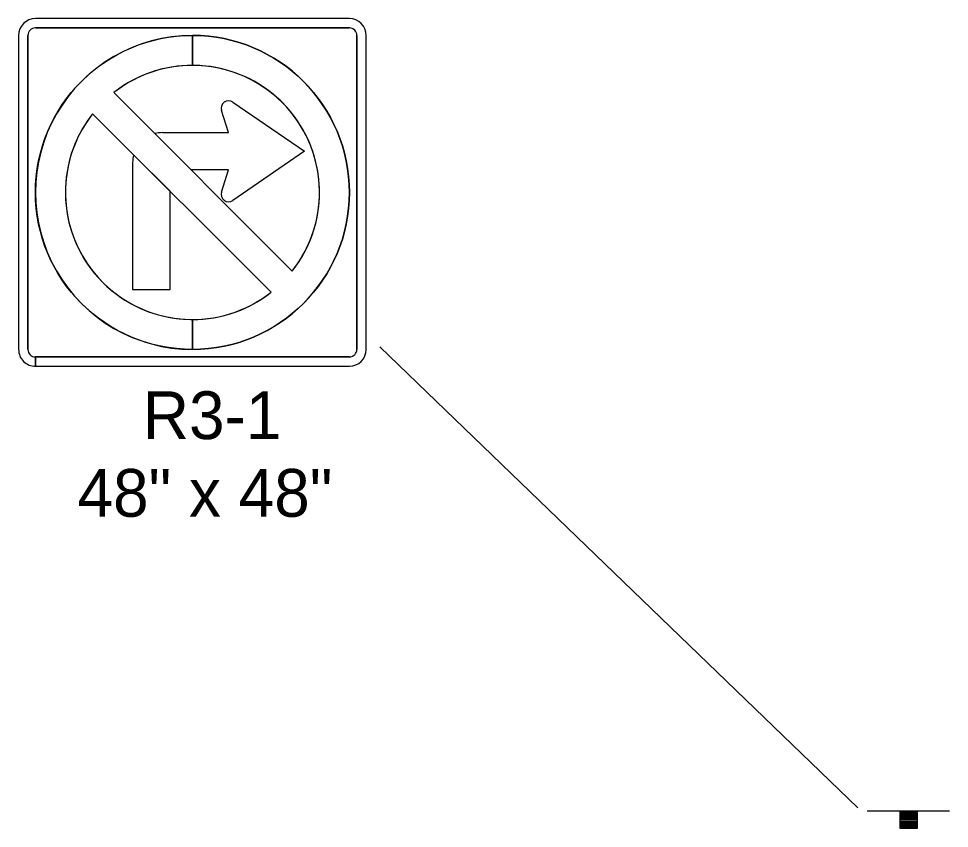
# Model space of a CAD drawing. Extents: x 10124 to 16850, y 7924 to 12166.
# Drawn here: x 12115.7 to 12427.5, y 11894.8 to 12166 of the extents above; entities that cross this region are included whole.
import ezdxf

# ---------------------------------------------------------------- set-up
doc = ezdxf.new("R2010")
doc.units = 0
for name, color, linetype in [('dsnStdLabel', 7, 'Continuous'), ('GSBWFILL', 7, 'Continuous'), ('GSCOLORFILL', 7, 'Continuous'), ('GSOUTLINE', 7, 'Continuous'), ('Level 2', 7, 'Continuous')]:
    doc.layers.add(name, color=color, linetype=linetype)

msp = doc.modelspace()

# ---------------------------------------------------------------- linework, layer by layer
at = {"layer": 'dsnStdLabel'}
for p, q in [((12226.51, 12165.98), (12121.35, 12165.98)), ((12226.51, 12165.98), (12121.35, 12165.98)), ((12121.35, 12165.98), (12121.35, 12165.97)), ((12226.51, 12165.98), (12121.35, 12165.98)), ((12121.35, 12165.98), (12121.35, 12165.97)), ((12226.51, 12165.98), (12226.51, 12165.98)), ((12226.51, 12165.98), (12226.51, 12165.98)), ((12226.51, 12162.85), (12121.35, 12162.85)), ((12121.35, 12162.84), (12121.36, 12162.85)), ((12121.35, 12162.84), (12121.36, 12162.85)), ((12121.36, 12162.85), (12226.52, 12162.85)), ((12121.36, 12162.85), (12226.52, 12162.85)), ((12226.52, 12162.85), (12226.51, 12162.85)), ((12226.52, 12162.85), (12226.51, 12162.85)), ((12115.72, 12160.34), (12115.72, 12055.18)), ((12115.72, 12160.34), (12115.72, 12160.34)), ((12115.72, 12160.34), (12115.72, 12055.18)), ((12115.72, 12160.34), (12115.72, 12160.34)), ((12115.72, 12160.34), (12115.72, 12055.18)), ((12118.85, 12160.34), (12118.85, 12055.18)), ((12118.85, 12055.18), (12118.85, 12160.34)), ((12118.85, 12160.34), (12118.85, 12160.34)), ((12118.85, 12055.18), (12118.85, 12160.34)), ((12118.85, 12160.34), (12118.85, 12160.34)), ((12173.94, 12150.34), (12173.94, 12160.35)), ((12173.96, 12160.35), (12173.96, 12150.34)), ((12173.96, 12160.35), (12173.96, 12160.35)), ((12229.02, 12055.18), (12229.02, 12160.34)), ((12229.02, 12160.34), (12229.02, 12160.34)), ((12229.02, 12160.34), (12229.02, 12055.18)), ((12229.02, 12160.34), (12229.02, 12160.34)), ((12229.02, 12160.34), (12229.02, 12055.18)), ((12232.15, 12055.18), (12232.15, 12160.34)), ((12232.15, 12055.18), (12232.15, 12160.34)), ((12232.15, 12160.34), (12232.15, 12160.34)), ((12232.15, 12055.18), (12232.15, 12160.34)), ((12232.15, 12160.34), (12232.15, 12160.34)), ((12147.58, 12141.2), (12207.37, 12081.43)), ((12147.58, 12141.2), (12207.37, 12081.43)), ((12207.37, 12081.43), (12147.58, 12141.2)), ((12140.5, 12134.12), (12200.29, 12074.35)), ((12140.5, 12134.12), (12200.29, 12074.35)), ((12140.5, 12134.12), (12200.29, 12074.35)), ((12186.04, 12127.8), (12183.69, 12135.18)), ((12186.04, 12127.8), (12183.69, 12135.18)), ((12186.04, 12127.8), (12183.69, 12135.18)), ((12163.92, 12127.8), (12186.04, 12127.8)), ((12163.92, 12127.8), (12186.04, 12127.8)), ((12163.92, 12127.8), (12186.04, 12127.8)), ((12153.9, 12117.79), (12153.9, 12075.23)), ((12153.9, 12117.79), (12153.9, 12075.23)), ((12153.9, 12117.79), (12153.9, 12075.23)), ((12173.94, 12055.2), (12173.94, 12065.21)), ((12173.96, 12065.21), (12173.96, 12055.2)), ((12115.72, 12055.18), (12115.72, 12055.17)), ((12115.72, 12055.18), (12115.72, 12055.17)), ((12118.85, 12055.17), (12118.85, 12055.18)), ((12118.85, 12055.17), (12118.85, 12055.18)), ((12121.35, 12052.67), (12226.52, 12052.67)), ((12121.35, 12049.54), (12121.35, 12052.67)), ((12121.35, 12052.67), (12121.36, 12052.67)), ((12121.35, 12049.54), (12121.35, 12052.67)), ((12121.35, 12052.67), (12121.36, 12052.67)), ((12226.52, 12052.67), (12121.39, 12052.67)), ((12121.39, 12052.67), (12121.39, 12049.54)), ((12226.52, 12052.67), (12121.39, 12052.67)), ((12121.39, 12052.67), (12121.39, 12049.54)), ((12226.52, 12052.67), (12226.52, 12052.67)), ((12226.52, 12052.67), (12226.52, 12052.67)), ((12229.02, 12055.18), (12229.02, 12055.18)), ((12229.02, 12055.18), (12229.02, 12055.18)), ((12232.15, 12055.18), (12232.15, 12055.18)), ((12232.15, 12055.18), (12232.15, 12055.18)), ((12121.35, 12049.54), (12226.52, 12049.54)), ((12121.36, 12049.54), (12121.35, 12049.54)), ((12121.36, 12049.54), (12121.35, 12049.54)), ((12121.39, 12049.54), (12226.52, 12049.54)), ((12121.39, 12049.54), (12226.52, 12049.54)), ((12226.52, 12049.54), (12226.52, 12049.54)), ((12226.52, 12049.54), (12226.52, 12049.54))]:
    msp.add_line(p, q, dxfattribs=at)
for points in [[(12187.5, 12138), (12211.49, 12121.54), (12187.5, 12105.09)], [(12187.5, 12138), (12211.49, 12121.54), (12187.5, 12105.09)], [(12187.5, 12138), (12211.49, 12121.54), (12187.5, 12105.09)], [(12183.69, 12107.9), (12186.04, 12115.29), (12173.51, 12115.29), (12161.33, 12127.46)], [(12183.69, 12107.9), (12186.04, 12115.29), (12173.51, 12115.29), (12161.33, 12127.46)], [(12183.69, 12107.9), (12186.04, 12115.29), (12173.51, 12115.29), (12161.33, 12127.46)], [(12153.9, 12075.23), (12166.43, 12075.23), (12166.43, 12108.2), (12154.24, 12120.38)], [(12153.9, 12075.23), (12166.43, 12075.23), (12166.43, 12108.2), (12154.24, 12120.38)], [(12153.9, 12075.23), (12166.43, 12075.23), (12166.43, 12108.2), (12154.24, 12120.38)]]:
    msp.add_lwpolyline(points, dxfattribs=at)
for centre, radius, start, end in [((12121.35, 12160.34), 5.63, 90.0016, 180.0016), ((12121.35, 12160.34), 5.63, 90.0016, 180.0016), ((12121.35, 12160.34), 5.63, 90.0016, 180.0016), ((12226.51, 12160.34), 5.63, 0.0016, 90.0016), ((12226.51, 12160.34), 5.63, 0.0016, 90.0016), ((12226.51, 12160.34), 5.63, 0.0016, 90.0016), ((12121.35, 12160.34), 2.5, 90.0016, 180.0016), ((12121.35, 12160.34), 2.5, 90.0016, 180.0016), ((12121.35, 12160.34), 2.5, 90.0016, 180.0016), ((12226.51, 12160.34), 2.5, 0.0016, 90.0016), ((12226.51, 12160.34), 2.5, 0.0016, 90.0016), ((12226.51, 12160.34), 2.5, 0.0016, 90.0016), ((12121.36, 12055.17), 5.63, 180.0016, 270.0016), ((12121.36, 12055.17), 5.63, 180.0016, 270.0016), ((12121.36, 12055.17), 5.63, 180.0016, 270.0016), ((12121.36, 12055.17), 2.5, 180.0016, 270.0016), ((12121.36, 12055.17), 2.5, 180.0016, 270.0016), ((12121.36, 12055.17), 2.5, 180.0016, 270.0016), ((12226.52, 12055.18), 5.63, 270.0016, 0.0016), ((12226.52, 12055.18), 2.5, 270.0016, 0.0016), ((12226.52, 12055.18), 5.63, 270.0016, 0.0016), ((12226.52, 12055.18), 2.5, 270.0016, 0.0016), ((12226.52, 12055.18), 5.63, 270.0016, 0.0016), ((12226.52, 12055.18), 2.5, 270.0016, 0.0016)]:
    msp.add_arc(centre, radius, start, end, dxfattribs=at)
msp.add_ellipse((12173.94, 12107.77), major_axis=(52.58, 0), ratio=0.99995, dxfattribs=at)
msp.add_ellipse((12173.94, 12107.77), major_axis=(52.58, 0), ratio=0.99995, dxfattribs=at)
for centre, major_axis, start_param, end_param in [((12173.94, 12107.77), (52.58, 0), 1.570796, 4.712389), ((12173.94, 12107.77), (52.58, 0), 4.712839, 7.853532), ((12173.94, 12107.77), (42.56, 0), 5.615707, 8.52146), ((12173.94, 12107.77), (42.56, 0), 5.615689, 8.521478), ((12173.94, 12107.77), (42.56, 0), 1.570796, 2.238292), ((12173.94, 12107.77), (42.56, 0), 5.615689, 7.853426), ((12186.08, 12135.94), (-2.5, 0), 4.111136, 6.59038), ((12186.08, 12135.94), (-2.5, 0), 4.111136, 6.59038), ((12186.08, 12135.94), (-2.5, 0), 4.111136, 6.59038), ((12173.94, 12107.77), (42.56, 0), 2.474115, 5.379867), ((12173.94, 12107.77), (42.56, 0), 2.474097, 5.379885), ((12173.94, 12107.77), (42.56, 0), 2.474097, 4.712389), ((12163.92, 12117.79), (-10.01, 0), 4.712389, 4.974188), ((12163.92, 12117.79), (-10.01, 0), 4.712389, 4.974188), ((12163.92, 12117.79), (-10.01, 0), 4.712389, 4.974188), ((12163.92, 12117.79), (-10.01, 0), 6.021386, 6.283185), ((12163.92, 12117.79), (-10.01, 0), 6.021386, 6.283185), ((12163.92, 12117.79), (-10.01, 0), 6.021386, 6.283185), ((12186.08, 12107.15), (2.5, 0), 2.834398, 5.313641), ((12186.08, 12107.15), (2.5, 0), 2.834398, 5.313641), ((12186.08, 12107.15), (2.5, 0), 2.834398, 5.313641), ((12173.94, 12107.77), (42.56, 0), 4.712945, 5.379885)]:
    msp.add_ellipse(centre, major_axis=major_axis, ratio=0.99995, start_param=start_param, end_param=end_param, dxfattribs=at)
at = {"layer": 'GSBWFILL'}
for p, q in [((12147.58, 12141.2), (12207.37, 12081.43)), ((12140.5, 12134.12), (12200.29, 12074.35)), ((12186.04, 12127.8), (12183.69, 12135.18)), ((12163.92, 12127.8), (12186.04, 12127.8)), ((12153.9, 12117.79), (12153.9, 12075.23))]:
    msp.add_line(p, q, dxfattribs=at)
for points in [[(12187.5, 12138), (12211.49, 12121.54), (12187.5, 12105.09)], [(12183.69, 12107.9), (12186.04, 12115.29), (12173.51, 12115.29), (12161.33, 12127.46)], [(12153.9, 12075.23), (12166.43, 12075.23), (12166.43, 12108.2), (12154.24, 12120.38)]]:
    msp.add_lwpolyline(points, dxfattribs=at)
msp.add_ellipse((12173.94, 12107.77), major_axis=(52.58, 0), ratio=0.99995, dxfattribs=at)
for centre, major_axis, start_param, end_param in [((12173.94, 12107.77), (42.56, 0), 5.615689, 8.521478), ((12186.08, 12135.94), (-2.5, 0), 4.111136, 6.59038), ((12173.94, 12107.77), (42.56, 0), 2.474097, 5.379885), ((12163.92, 12117.79), (-10.01, 0), 4.712389, 4.974188), ((12163.92, 12117.79), (-10.01, 0), 6.021386, 6.283185), ((12186.08, 12107.15), (2.5, 0), 2.834398, 5.313641)]:
    msp.add_ellipse(centre, major_axis=major_axis, ratio=0.99995, start_param=start_param, end_param=end_param, dxfattribs=at)
at = {"layer": 'GSCOLORFILL'}
for p, q in [((12173.94, 12150.34), (12173.94, 12160.35)), ((12173.96, 12160.35), (12173.96, 12150.34)), ((12173.96, 12160.35), (12173.96, 12160.35)), ((12207.37, 12081.43), (12147.58, 12141.2)), ((12140.5, 12134.12), (12200.29, 12074.35)), ((12186.04, 12127.8), (12183.69, 12135.18)), ((12163.92, 12127.8), (12186.04, 12127.8)), ((12153.9, 12117.79), (12153.9, 12075.23)), ((12173.94, 12055.2), (12173.94, 12065.21)), ((12173.96, 12065.21), (12173.96, 12055.2))]:
    msp.add_line(p, q, dxfattribs=at)
for points in [[(12187.5, 12138), (12211.49, 12121.54), (12187.5, 12105.09)], [(12183.69, 12107.9), (12186.04, 12115.29), (12173.51, 12115.29), (12161.33, 12127.46)], [(12153.9, 12075.23), (12166.43, 12075.23), (12166.43, 12108.2), (12154.24, 12120.38)]]:
    msp.add_lwpolyline(points, dxfattribs=at)
for centre, major_axis, start_param, end_param in [((12173.94, 12107.77), (52.58, 0), 1.570796, 4.712389), ((12173.94, 12107.77), (52.58, 0), 4.712839, 7.853532), ((12173.94, 12107.77), (42.56, 0), 1.570796, 2.238292), ((12173.94, 12107.77), (42.56, 0), 5.615689, 7.853426), ((12186.08, 12135.94), (-2.5, 0), 4.111136, 6.59038), ((12173.94, 12107.77), (42.56, 0), 2.474097, 4.712389), ((12163.92, 12117.79), (-10.01, 0), 4.712389, 4.974188), ((12163.92, 12117.79), (-10.01, 0), 6.021386, 6.283185), ((12186.08, 12107.15), (2.5, 0), 2.834398, 5.313641), ((12173.94, 12107.77), (42.56, 0), 4.712945, 5.379885)]:
    msp.add_ellipse(centre, major_axis=major_axis, ratio=0.99995, start_param=start_param, end_param=end_param, dxfattribs=at)
at = {"layer": 'GSOUTLINE'}
for p, q in [((12147.58, 12141.2), (12207.37, 12081.43)), ((12140.5, 12134.12), (12200.29, 12074.35)), ((12186.04, 12127.8), (12183.69, 12135.18)), ((12163.92, 12127.8), (12186.04, 12127.8)), ((12153.9, 12117.79), (12153.9, 12075.23))]:
    msp.add_line(p, q, dxfattribs=at)
for points in [[(12187.5, 12138), (12211.49, 12121.54), (12187.5, 12105.09)], [(12183.69, 12107.9), (12186.04, 12115.29), (12173.51, 12115.29), (12161.33, 12127.46)], [(12153.9, 12075.23), (12166.43, 12075.23), (12166.43, 12108.2), (12154.24, 12120.38)]]:
    msp.add_lwpolyline(points, dxfattribs=at)
msp.add_ellipse((12173.94, 12107.77), major_axis=(52.58, 0), ratio=0.99995, dxfattribs=at)
for centre, major_axis, start_param, end_param in [((12173.94, 12107.77), (42.56, 0), 5.615707, 8.52146), ((12186.08, 12135.94), (-2.5, 0), 4.111136, 6.59038), ((12173.94, 12107.77), (42.56, 0), 2.474115, 5.379867), ((12163.92, 12117.79), (-10.01, 0), 4.712389, 4.974188), ((12163.92, 12117.79), (-10.01, 0), 6.021386, 6.283185), ((12186.08, 12107.15), (2.5, 0), 2.834398, 5.313641)]:
    msp.add_ellipse(centre, major_axis=major_axis, ratio=0.99995, start_param=start_param, end_param=end_param, dxfattribs=at)
at = {"layer": 'Level 2'}
for p, q in [((12236.74, 12056.07), (12396.79, 11901.67)), ((12427.47, 11900.51), (12399.97, 11900.51)), ((12411.02, 11900.09), (12416.6, 11900.09)), ((12416.6, 11899.81), (12411.02, 11899.81)), ((12411.02, 11899.55), (12416.6, 11899.55)), ((12416.6, 11899.29), (12411.02, 11899.29)), ((12411.02, 11899.06), (12416.6, 11899.06)), ((12416.6, 11898.85), (12411.02, 11898.85)), ((12411.02, 11898.52), (12416.6, 11898.52)), ((12416.6, 11898.25), (12411.02, 11898.25)), ((12411.02, 11898.03), (12416.6, 11898.05)), ((12416.6, 11897.71), (12411.02, 11897.71)), ((12411.02, 11897.34), (12416.6, 11897.34)), ((12416.6, 11896.9), (12411.02, 11896.9)), ((12411.02, 11896.68), (12416.6, 11896.7)), ((12416.6, 11896.27), (12411.02, 11896.25)), ((12411.02, 11896.04), (12416.6, 11896.04)), ((12416.6, 11895.72), (12411.02, 11895.72)), ((12411.02, 11895.5), (12416.6, 11895.5)), ((12416.6, 11895.18), (12411.02, 11895.18))]:
    msp.add_line(p, q, dxfattribs=at)
msp.add_lwpolyline([(12411.02, 11900.41), (12416.64, 11900.41), (12416.64, 11894.79), (12411.02, 11894.79)], close=True, dxfattribs=at)

# ---------------------------------------------------------------- texts
at = {"layer": 'dsnStdLabel'}
for s, p in [('R3-1', (12157.35, 12025.15)), ('48" x 48"', (12135.45, 11999.15))]:
    msp.add_text(s, height=16, dxfattribs=at).set_placement(p)

doc.saveas('drawing.dxf')
